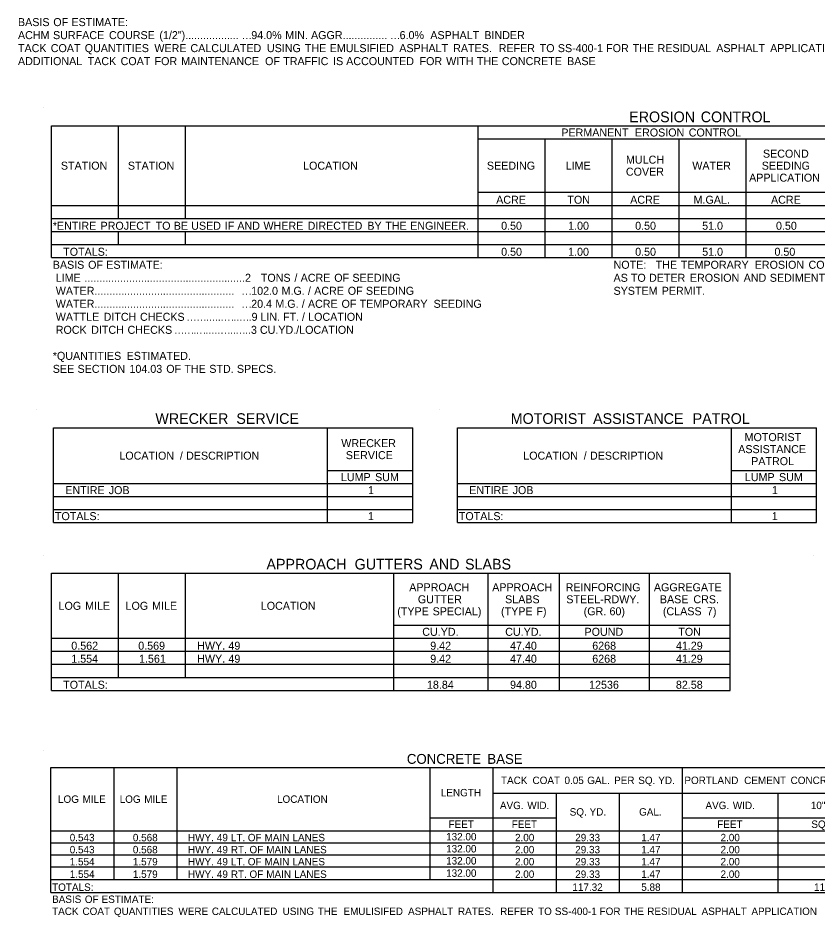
# Model space of a CAD drawing. Extents: x 107 to 7866, y 32 to 1473.
# Drawn here: x 2173 to 2772, y 40 to 714 of the extents above; entities that cross this region are included whole.
import ezdxf

# ---------------------------------------------------------------- set-up
doc = ezdxf.new("R2010")
doc.units = 0
doc.layers.add('Default', color=7, linetype='Continuous')
doc.layers.add('R_No Plot', color=7, linetype='Continuous')

msp = doc.modelspace()

# ---------------------------------------------------------------- linework, layer by layer
at = {"layer": 'Default'}
for p, q in [((2192.59, 646.36), (2192.59, 646.36)), ((2198.44, 632.71), (3178.81, 632.71)), ((2198.44, 534.24), (2198.44, 632.71)), ((2198.44, 534.24), (2198.44, 632.71)), ((2248.66, 563.49), (2248.66, 632.71)), ((2298.87, 563.49), (2298.87, 632.71)), ((2518.24, 534.24), (2518.24, 632.71)), ((2518.24, 622.96), (3178.81, 622.96)), ((2568.46, 534.24), (2568.46, 622.96)), ((2618.67, 534.24), (2618.67, 622.96)), ((2668.88, 534.24), (2668.88, 622.96)), ((2719.09, 534.24), (2719.09, 622.96)), ((2518.24, 582.99), (3178.81, 582.99)), ((2568.46, 534.24), (2568.46, 582.99)), ((2618.67, 543.99), (2618.67, 582.99)), ((2668.88, 543.99), (2668.88, 582.99)), ((2719.09, 543.99), (2719.09, 582.99)), ((2198.44, 573.24), (3178.81, 573.24)), ((2248.66, 563.49), (2248.66, 573.24)), ((2298.87, 573.24), (2518.24, 573.24)), ((2298.87, 563.49), (2298.87, 573.24)), ((2518.24, 563.49), (2518.24, 573.24)), ((2198.44, 563.49), (3178.81, 563.49)), ((2198.44, 553.74), (3178.81, 553.74)), ((2248.66, 543.99), (2248.66, 553.74)), ((2248.66, 543.99), (2248.66, 553.74)), ((2298.87, 543.99), (2298.87, 553.74)), ((2298.87, 543.99), (2298.87, 553.74)), ((2518.24, 534.24), (2518.24, 553.74)), ((2198.44, 543.99), (3178.81, 543.99)), ((2568.46, 543.99), (2779.54, 543.99)), ((2198.44, 534.24), (3178.81, 534.24)), ((2186.88, 420.26), (2186.88, 420.26)), ((2489.55, 420.26), (2489.55, 420.26)), ((2200.05, 406.61), (2469.15, 406.61)), ((2200.05, 335.43), (2200.05, 406.61)), ((2200.05, 335.43), (2200.05, 406.61)), ((2405.28, 335.43), (2405.28, 406.61)), ((2469.15, 335.43), (2469.15, 406.61)), ((2469.15, 335.43), (2469.15, 406.61)), ((2502.71, 406.61), (2771.81, 406.61)), ((2502.71, 335.43), (2502.71, 406.61)), ((2502.71, 335.43), (2502.71, 406.61)), ((2707.95, 335.43), (2707.95, 406.61)), ((2771.81, 335.43), (2771.81, 406.61)), ((2771.81, 335.43), (2771.81, 406.61)), ((2405.28, 374.43), (2469.15, 374.43)), ((2707.95, 374.43), (2771.81, 374.43)), ((2200.05, 364.68), (2469.15, 364.68)), ((2502.71, 364.68), (2771.81, 364.68)), ((2200.05, 354.93), (2469.15, 354.93)), ((2502.71, 354.93), (2771.81, 354.93)), ((2200.05, 345.18), (2469.15, 345.18)), ((2502.71, 345.18), (2771.81, 345.18)), ((2200.05, 335.43), (2469.15, 335.43)), ((2502.71, 335.43), (2771.81, 335.43)), ((2192.59, 311.15), (2192.59, 311.15)), ((2198.44, 297.5), (2706.91, 297.5)), ((2198.44, 209.75), (2198.44, 297.5)), ((2198.44, 209.75), (2198.44, 297.5)), ((2248.66, 219.5), (2248.66, 297.5)), ((2298.87, 219.5), (2298.87, 297.5)), ((2454.87, 209.75), (2454.87, 297.5)), ((2525.56, 209.75), (2525.56, 297.5)), ((2579.18, 209.75), (2579.18, 297.5)), ((2646.46, 209.75), (2646.46, 297.5)), ((2706.91, 209.75), (2706.91, 297.5)), ((2454.87, 258.5), (2706.91, 258.5)), ((2525.56, 209.75), (2525.56, 258.5)), ((2579.18, 209.75), (2579.18, 258.5)), ((2646.46, 209.75), (2646.46, 258.5)), ((2706.91, 209.75), (2706.91, 258.5)), ((2198.44, 248.75), (2706.91, 248.75)), ((2248.66, 219.5), (2248.66, 248.75)), ((2298.87, 219.5), (2298.87, 248.75)), ((2454.87, 209.75), (2454.87, 248.75)), ((2198.44, 239), (2706.91, 239)), ((2198.44, 229.25), (2706.91, 229.25)), ((2198.44, 219.5), (2706.91, 219.5)), ((2198.44, 209.75), (2706.91, 209.75)), ((2192.59, 164.87), (2192.59, 164.87)), ((2198.01, 151.87), (2820.2, 151.87)), ((2198.01, 58.34), (2198.01, 151.87)), ((2198.01, 58.34), (2198.01, 151.87)), ((2245.32, 68.09), (2245.32, 151.87)), ((2292.62, 68.09), (2292.62, 151.87)), ((2482.2, 68.09), (2482.2, 151.87)), ((2529.51, 58.34), (2529.51, 151.87)), ((2671.43, 58.34), (2671.43, 151.87)), ((2529.51, 132.73), (2671.43, 132.73)), ((2529.51, 132.73), (2624.12, 132.73)), ((2576.82, 58.34), (2576.82, 132.73)), ((2624.12, 132.73), (2820.2, 132.73)), ((2624.12, 58.34), (2624.12, 132.73)), ((2742.93, 58.34), (2742.93, 132.73)), ((2482.2, 114.32), (2576.82, 114.32)), ((2576.82, 104.57), (2576.82, 114.32)), ((2671.43, 114.32), (2820.2, 114.32)), ((2742.93, 68.09), (2742.93, 114.32)), ((2198.01, 104.57), (2292.62, 104.57)), ((2198.01, 104.57), (2245.32, 104.57)), ((2245.32, 104.57), (2576.82, 104.57)), ((2482.2, 68.09), (2482.2, 104.57)), ((2529.51, 104.57), (2576.82, 104.57)), ((2529.51, 58.34), (2529.51, 104.57)), ((2576.82, 104.57), (2820.2, 104.57)), ((2576.82, 104.57), (2624.12, 104.57)), ((2624.12, 104.57), (2820.2, 104.57)), ((2624.12, 68.09), (2624.12, 104.57)), ((2198.01, 95.54), (2820.2, 95.54)), ((2198.01, 86.51), (2820.2, 86.51)), ((2198.01, 77.48), (2820.2, 77.48)), ((2198.01, 68.09), (2820.2, 68.09)), ((2198.01, 68.09), (2820.2, 68.09)), ((2576.82, 58.34), (2576.82, 68.09)), ((2198.01, 58.34), (2820.2, 58.34))]:
    msp.add_line(p, q, dxfattribs=at)
at = {"layer": 'R_No Plot'}
msp.add_line((2769.84, 311.15), (2769.84, 311.15), dxfattribs=at)

# ---------------------------------------------------------------- texts
at = {"layer": 'Default'}
for s, height, p in [('BASIS', 6, (2173.32, 707.56)), (' OF', 6, (2197.58, 707.56)), (' ESTIMATE:', 6, (2211.17, 707.56)), ('ACHM', 6, (2173.32, 697.81)), (' SURFACE', 6, (2197.38, 697.81)), (' COURSE', 6, (2239.32, 697.81)), (' (1/2")..................', 6, (2277.08, 697.81)), ('94.0%', 6, (2348.17, 697.81)), (' MIN.', 6, (2371.42, 697.81)), (' AGGR...............', 6, (2390.71, 697.81)), ('6.0%', 6, (2459.31, 697.81)), ('  ASPHALT', 6, (2477.89, 697.81)), (' BINDER', 6, (2520.58, 697.81)), ('TACK', 6, (2173.32, 688.06)), (' COAT', 6, (2195.67, 688.06)), (' QUANTITIES', 6, (2221.12, 688.06)), (' WERE', 6, (2273.32, 688.06)), (' CALCULATED', 6, (2300.35, 688.06)), ('…', 6, (2340.78, 697.81)), (' USING', 6, (2357.67, 688.06)), (' THE', 6, (2386.02, 688.06)), (' EMULSIFIED', 6, (2404.67, 688.06)), ('…', 6, (2451.91, 697.81)), (' ASPHALT', 6, (2456.86, 688.06)), (' RATES.', 6, (2497.23, 688.06)), ('  REFER', 6, (2529.11, 688.06)), (' TO', 6, (2562.07, 688.06)), (' SS-400-1', 6, (2575.66, 688.06)), (' FOR', 6, (2611.85, 688.06)), (' THE', 6, (2631.77, 688.06)), (' RESIDUAL', 6, (2650.42, 688.06)), (' ASPHALT', 6, (2694.38, 688.06)), (' APPLICATION', 6, (2734.75, 688.06)), ('ADDITIONAL', 6, (2173.32, 678.31)), (' TACK', 6, (2223.34, 678.31)), (' COAT', 6, (2248.01, 678.31)), (' FOR', 6, (2273.46, 678.31)), (' MAINTENANCE', 6, (2293.37, 678.31)), (' OF', 6, (2356.27, 678.31)), (' TRAFFIC', 6, (2369.86, 678.31)), (' IS', 6, (2407.25, 678.31)), (' ACCOUNTED', 6, (2417.06, 678.31)), (' FOR', 6, (2472.04, 678.31)), (' WITH', 6, (2491.96, 678.31)), (' THE', 6, (2515.02, 678.31)), (' CONCRETE', 6, (2533.67, 678.31)), (' BASE', 6, (2582.6, 678.31)), ('EROSION', 8, (2631.35, 635.54)), (' CONTROL', 8, (2682.01, 635.54)), ('PERMANENT', 6, (2580.5, 624.84)), (' EROSION', 6, (2633.43, 624.84)), (' CONTROL', 6, (2673.76, 624.84)), ('SECOND', 6, (2731.59, 608.97)), ('MULCH', 6, (2628.96, 604.47)), ('STATION', 6, (2205.49, 599.97)), ('STATION', 6, (2255.7, 599.97)), ('LOCATION', 6, (2387, 599.97)), ('SEEDING', 6, (2524.73, 599.97)), ('LIME', 6, (2583.76, 599.97)), ('COVER', 6, (2628.89, 595.47)), ('WATER', 6, (2678.64, 599.97)), ('SEEDING', 6, (2730.7, 599.97)), ('APPLICATION', 6, (2721.24, 590.97)), ('ACRE', 6, (2531.68, 574.44)), ('TON', 6, (2585.05, 574.44)), ('ACRE', 6, (2632.1, 574.44)), ('M.GAL.', 6, (2679.61, 574.44)), ('ACRE', 6, (2737.65, 574.44)), ('*ENTIRE', 6, (2199.42, 554.94)), (' PROJECT', 6, (2232.98, 554.94)), (' TO', 6, (2274.27, 554.94)), (' BE', 6, (2287.86, 554.94)), (' USED', 6, (2300.93, 554.94)), (' IF', 6, (2326.1, 554.94)), (' AND', 6, (2335.5, 554.94)), (' WHERE', 6, (2355.08, 554.94)), (' DIRECTED', 6, (2388.17, 554.94)), (' BY', 6, (2432.9, 554.94)), (' THE', 6, (2446.35, 554.94)), (' ENGINEER.', 6, (2465, 554.94)), ('0.50', 6, (2535.4, 554.94)), ('1.00', 6, (2585.61, 554.94)), ('0.50', 6, (2635.82, 554.94)), ('51.0', 6, (2686.03, 554.94)), ('0.50', 6, (2741.37, 554.94)), ('TOTALS:', 6, (2207.22, 535.44)), ('0.50', 6, (2535.4, 535.44)), ('1.00', 6, (2585.61, 535.44)), ('0.50', 6, (2635.83, 535.44)), ('51.0', 6, (2686.04, 535.44)), ('0.50', 6, (2740.21, 535.44)), ('BASIS', 6, (2199.42, 525.69)), (' OF', 6, (2223.68, 525.69)), (' ESTIMATE:', 6, (2237.27, 525.69)), ('NOTE:', 6, (2619.64, 525.69)), ('   THE', 6, (2644.53, 525.69)), (' TEMPORARY', 6, (2667.84, 525.69)), (' EROSION', 6, (2723.21, 525.69)), (' CONTROL', 6, (2763.52, 525.69)), (' LIME', 6, (2199.42, 515.94)), (' ......................................................2', 6, (2220.86, 515.94)), (' TONS', 6, (2353.1, 515.94)), (' /', 6, (2378.28, 515.94)), (' ACRE', 6, (2382.94, 515.94)), (' OF', 6, (2408.12, 515.94)), (' SEEDING', 6, (2421.71, 515.94)), ('AS', 6, (2619.64, 515.94)), (' TO', 6, (2630.39, 515.94)), (' DETER', 6, (2643.99, 515.94)), (' EROSION', 6, (2674.62, 515.94)), (' AND', 6, (2714.93, 515.94)), (' SEDIMENTATION', 6, (2734.51, 515.94)), (' WATER...............................................', 6, (2199.42, 506.19)), ('102.0', 6, (2348.09, 506.19)), (' M.G.', 6, (2368.66, 506.19)), (' /', 6, (2388.41, 506.19)), (' ACRE', 6, (2393.07, 506.19)), (' OF', 6, (2418.25, 506.19)), (' SEEDING', 6, (2431.84, 506.19)), ('SYSTEM', 6, (2619.64, 506.19)), (' PERMIT.', 6, (2653.49, 506.19)), ('…', 6, (2340.69, 506.19)), (' WATER...............................................', 6, (2199.42, 496.44)), ('20.4', 6, (2348.09, 496.44)), (' M.G.', 6, (2363.99, 496.44)), (' /', 6, (2383.75, 496.44)), (' ACRE', 6, (2388.41, 496.44)), (' OF', 6, (2413.58, 496.44)), (' TEMPORARY', 6, (2427.17, 496.44)), (' SEEDING', 6, (2482.54, 496.44)), (' WATTLE', 6, (2199.42, 486.69)), (' DITCH', 6, (2235.3, 486.69)), (' CHECKS', 6, (2262.56, 486.69)), ('…', 6, (2340.69, 496.44)), ('.9', 6, (2346.15, 486.69)), (' LIN.', 6, (2352.77, 486.69)), (' FT.', 6, (2369.74, 486.69)), (' /', 6, (2383.9, 486.69)), (' LOCATION', 6, (2388.56, 486.69)), ('…', 6, (2299.4, 486.69)), ('…', 6, (2306.8, 486.69)), ('......', 6, (2314.2, 486.69)), ('…', 6, (2327.43, 486.69)), ('..', 6, (2334.83, 486.69)), ('…', 6, (2338.75, 486.69)), (' ROCK', 6, (2199.42, 476.94)), (' DITCH', 6, (2225.95, 476.94)), (' CHECKS', 6, (2253.22, 476.94)), ('..3', 6, (2343.47, 476.94)), (' CU.YD./LOCATION', 6, (2352.41, 476.94)), ('…', 6, (2290.05, 476.94)), ('…', 6, (2297.45, 476.94)), ('.', 6, (2304.85, 476.94)), ('…', 6, (2306.44, 476.94)), ('.....', 6, (2313.84, 476.94)), ('…', 6, (2324.75, 476.94)), ('..', 6, (2332.15, 476.94)), ('…', 6, (2336.07, 476.94)), ('*QUANTITIES', 6, (2199.42, 457.44)), (' ESTIMATED.', 6, (2252.55, 457.44)), ('SEE', 6, (2199.42, 447.69)), (' SECTION', 6, (2215.75, 447.69)), (' 104.03', 6, (2254.66, 447.69)), (' OF', 6, (2282.23, 447.69)), (' THE', 6, (2295.82, 447.69)), (' STD.', 6, (2314.47, 447.69)), (' SPECS.', 6, (2335.16, 447.69)), ('WRECKER', 8, (2276.28, 409.43)), (' SERVICE', 8, (2333.98, 409.43)), ('MOTORIST', 8, (2542.56, 409.43)), (' ASSISTANCE', 8, (2601.32, 409.43)), (' PATROL', 8, (2675.93, 409.43)), ('WRECKER', 6, (2415.58, 392.02)), ('MOTORIST', 6, (2717.85, 396.52)), ('ASSISTANCE', 6, (2713.07, 387.52)), ('LOCATION', 6, (2249.3, 382.65)), (' /', 6, (2292.41, 382.65)), (' DESCRIPTION', 6, (2297.08, 382.65)), ('SERVICE', 6, (2419.02, 383.02)), ('LOCATION', 6, (2551.97, 382.65)), (' /', 6, (2595.08, 382.65)), (' DESCRIPTION', 6, (2599.74, 382.65)), ('PATROL', 6, (2722.77, 378.52)), ('LUMP', 6, (2415.35, 366.56)), (' SUM', 6, (2438.72, 366.56)), ('LUMP', 6, (2718.02, 366.56)), (' SUM', 6, (2741.39, 366.56)), ('ENTIRE', 6, (2208.82, 356.81)), (' JOB', 6, (2239.12, 356.81)), ('1', 6, (2435.66, 356.81)), ('ENTIRE', 6, (2511.49, 356.81)), (' JOB', 6, (2541.78, 356.81)), ('1', 6, (2738.32, 356.81)), ('TOTALS:', 6, (2201.02, 337.31)), ('1', 6, (2435.56, 337.31)), ('TOTALS:', 6, (2503.69, 337.31)), ('1', 6, (2738.23, 337.31)), ('APPROACH', 8, (2359.52, 300.32)), (' GUTTERS', 8, (2422.64, 300.32)), (' AND', 8, (2478.61, 300.32)), (' SLABS', 8, (2505.38, 300.32)), ('APPROACH', 6, (2466.54, 284)), ('APPROACH', 6, (2528.7, 284)), ('REINFORCING', 6, (2583.73, 284)), ('AGGREGATE', 6, (2649.87, 284)), ('GUTTER', 6, (2473, 275)), ('SLABS', 6, (2538.37, 275)), ('STEEL-RDWY.', 6, (2584.23, 275)), ('BASE', 6, (2654.35, 275)), (' CRS.', 6, (2677.23, 275)), ('LOG', 6, (2203.75, 270.12)), (' MILE', 6, (2221.41, 270.12)), ('LOG', 6, (2253.96, 270.12)), (' MILE', 6, (2271.62, 270.12)), ('LOCATION', 6, (2355.31, 270.12)), ('(TYPE', 6, (2457.56, 266)), (' SPECIAL)', 6, (2481.84, 266)), ('(TYPE', 6, (2535.33, 266)), (' F)', 6, (2559.6, 266)), ('(GR.', 6, (2597.26, 266)), (' 60)', 6, (2614.38, 266)), ('(CLASS', 6, (2656.61, 266)), (' 7)', 6, (2687.41, 266)), ('CU.YD.', 6, (2476.29, 250.62)), ('CU.YD.', 6, (2538.45, 250.62)), ('POUND', 6, (2597.89, 250.62)), ('TON', 6, (2668.17, 250.62)), ('0.562', 6, (2213.29, 240.2)), ('0.569', 6, (2263.46, 240.2)), ('HWY.', 6, (2307.64, 240.2)), (' 49', 6, (2328.8, 240.2)), ('9.42', 6, (2482.28, 240.2)), ('47.40', 6, (2542.09, 240.2)), ('6268', 6, (2603.68, 240.2)), ('41.29', 6, (2666.38, 240.2)), ('1.554', 6, (2213.27, 230.45)), ('1.561', 6, (2264.05, 230.45)), ('HWY.', 6, (2307.64, 230.45)), (' 49', 6, (2328.8, 230.45)), ('9.42', 6, (2482.28, 230.45)), ('47.40', 6, (2542.09, 230.45)), ('6268', 6, (2603.68, 230.45)), ('41.29', 6, (2666.38, 230.45)), ('TOTALS:', 6, (2207.22, 210.95)), ('18.84', 6, (2479.82, 210.95)), ('94.80', 6, (2542.09, 210.95)), ('12536', 6, (2601.32, 210.95)), ('82.58', 6, (2666.38, 210.95)), ('CONCRETE', 7.407, (2464.76, 154.67)), (' BASE', 7.407, (2522.33, 154.67)), ('TACK', 5.556, (2535.29, 139.53)), (' COAT', 5.556, (2556.84, 139.53)), (' 0.05', 5.556, (2580.82, 139.53)), (' GAL.', 5.556, (2597.85, 139.53)), (' PER', 5.556, (2618.01, 139.53)), (' SQ.', 5.556, (2636.09, 139.53)), (' YD.', 5.556, (2651.09, 139.53)), ('PORTLAND', 5.556, (2672.72, 139.53)), (' CEMENT', 5.556, (2715.46, 139.53)), (' CONCRETE', 5.556, (2750.24, 139.53)), ('LENGTH', 5.556, (2490.2, 130.32)), ('LOG', 5.556, (2203.33, 125.44)), (' MILE', 5.556, (2219.68, 125.44)), ('LOG', 5.556, (2249.56, 125.44)), (' MILE', 5.556, (2265.91, 125.44)), ('LOCATION', 5.556, (2367.46, 125.44)), ('AVG.', 5.556, (2534.51, 120.75)), (' WID.', 5.556, (2552.95, 120.75)), ('SQ.', 5.556, (2586.77, 115.87)), (' YD.', 5.556, (2599.61, 115.87)), ('GAL.', 5.556, (2638.77, 115.87)), ('AVG.', 5.556, (2688.52, 120.75)), (' WID.', 5.556, (2706.97, 120.75)), ('10"', 5.556, (2767.46, 120.75)), ('FEET', 5.556, (2496.02, 106.66)), ('FEET', 5.556, (2543.32, 106.66)), ('FEET', 5.556, (2697.34, 106.66)), ('SQ.', 5.556, (2767.86, 106.66)), ('0.543', 5.556, (2212.13, 96.65)), ('0.568', 5.556, (2259.43, 96.65)), ('HWY.', 5.556, (2300.75, 96.65)), (' 49', 5.556, (2320.33, 96.65)), (' LT.', 5.556, (2330.78, 96.65)), (' OF', 5.556, (2343.47, 96.65)), (' MAIN', 5.556, (2356.05, 96.65)), (' LANES', 5.556, (2376.97, 96.65)), ('132.00', 5.556, (2494.18, 97.28)), ('2.00', 5.556, (2545.8, 96.65)), ('29.33', 5.556, (2590.94, 96.65)), ('1.47', 5.556, (2640.4, 96.65)), ('2.00', 5.556, (2699.81, 96.65)), ('0.543', 5.556, (2212.13, 87.62)), ('0.568', 5.556, (2259.43, 87.62)), ('HWY.', 5.556, (2300.75, 87.62)), (' 49', 5.556, (2320.33, 87.62)), (' RT.', 5.556, (2330.78, 87.62)), (' OF', 5.556, (2344.76, 87.62)), (' MAIN', 5.556, (2357.34, 87.62)), (' LANES', 5.556, (2378.27, 87.62)), ('132.00', 5.556, (2494.18, 88.25)), ('2.00', 5.556, (2545.8, 87.62)), ('29.33', 5.556, (2590.94, 87.62)), ('1.47', 5.556, (2640.4, 87.62)), ('2.00', 5.556, (2699.81, 87.62)), ('1.554', 5.556, (2212.14, 78.59)), ('1.579', 5.556, (2259.43, 78.59)), ('HWY.', 5.556, (2300.75, 78.59)), (' 49', 5.556, (2320.33, 78.59)), (' LT.', 5.556, (2330.78, 78.59)), (' OF', 5.556, (2343.47, 78.59)), (' MAIN', 5.556, (2356.05, 78.59)), (' LANES', 5.556, (2376.97, 78.59)), ('132.00', 5.556, (2494.18, 79.22)), ('2.00', 5.556, (2545.8, 78.59)), ('29.33', 5.556, (2590.94, 78.59)), ('1.47', 5.556, (2640.4, 78.59)), ('2.00', 5.556, (2699.81, 78.59)), ('1.554', 5.556, (2212.14, 69.21)), ('1.579', 5.556, (2259.43, 69.21)), ('HWY.', 5.556, (2300.75, 69.21)), (' 49', 5.556, (2320.33, 69.21)), (' RT.', 5.556, (2330.78, 69.21)), (' OF', 5.556, (2344.76, 69.21)), (' MAIN', 5.556, (2357.34, 69.21)), (' LANES', 5.556, (2378.27, 69.21)), ('132.00', 5.556, (2494.18, 70.01)), ('2.00', 5.556, (2545.8, 69.21)), ('29.33', 5.556, (2590.94, 69.21)), ('1.47', 5.556, (2640.4, 69.21)), ('2.00', 5.556, (2699.81, 69.21)), ('TOTALS:', 5.556, (2198.91, 59.46)), ('117.32', 5.556, (2588.8, 59.46)), ('5.88', 5.556, (2640.4, 59.46)), ('117.32', 5.556, (2769.9, 59.46)), ('BASIS', 5.556, (2198.91, 50.43)), (' OF', 5.556, (2221.38, 50.43)), (' ESTIMATE:', 5.556, (2233.96, 50.43)), ('TACK', 5.556, (2198.91, 41.4)), (' COAT', 5.556, (2219.6, 41.4)), (' QUANTITIES', 5.5556, (2243.17, 41.4)), (' WERE', 5.556, (2291.5, 41.4)), (' CALCULATED', 5.5556, (2316.53, 41.4)), (' USING', 5.556, (2369.6, 41.4)), (' THE', 5.556, (2395.86, 41.4)), ('  EMULISIFED', 5.5556, (2413.12, 41.4)), (' ASPHALT', 5.556, (2463.6, 41.4)), (' RATES.', 5.556, (2500.98, 41.4)), ('  REFER', 5.556, (2530.5, 41.4)), (' TO', 5.556, (2561.01, 41.4)), (' SS-400-1', 5.556, (2573.6, 41.4)), (' FOR', 5.556, (2607.11, 41.4)), (' THE', 5.556, (2625.55, 41.4)), (' RESIDUAL', 5.556, (2642.82, 41.4)), (' ASPHALT', 5.556, (2683.52, 41.4)), (' APPLICATION', 5.5556, (2720.9, 41.4))]:
    msp.add_text(s, height=height, dxfattribs=at).set_placement(p)

doc.saveas('drawing.dxf')
